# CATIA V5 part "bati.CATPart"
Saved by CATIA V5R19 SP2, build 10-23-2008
Part number: bati
Publications: "diametre bati"
Bounding box of the stored display mesh (mm): x -10 to 0, y -10 to 10, z -10 to 10
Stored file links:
  E:\IAO_2010\iao\IAO_MMS_Groupe2\IAO_MMS_Groupe2\OK\fvigouroux\vigouroux\vigouroux\bati.CATPart
  E:\IAO_2010\iao\IAO_MMS_Groupe2\IAO_MMS_Groupe2\OK\fvigouroux\vigouroux\vigouroux\mecanisme IAO.CATProduct
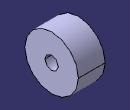
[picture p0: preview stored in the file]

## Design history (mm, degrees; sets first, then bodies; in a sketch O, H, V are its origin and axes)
Parameters
  `diametre bati` = 2.5 mm
Set1
  Plane1: linked copy from another document
  Point1: linked copy from another document
Body1 (main body)
  Sketch1 on Plane1, origin (0, 0, 0), H (0, 1, 0), V (0, 0, 1)
    circle A1 centre (0, 0) radius 10
    point P1 (0, 0)
    circle A2 centre (0, 0) radius 2.5
    reference projected point E1 (0, 0) from Point1
    distance E1 P1 = 0
    radius A2 = 2.5 {= `diametre bati`}
    radius A1 = 10
    coincidence: P1 H
  Pad1: profile Sketch1, direction (-1, 0, 0), length 10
